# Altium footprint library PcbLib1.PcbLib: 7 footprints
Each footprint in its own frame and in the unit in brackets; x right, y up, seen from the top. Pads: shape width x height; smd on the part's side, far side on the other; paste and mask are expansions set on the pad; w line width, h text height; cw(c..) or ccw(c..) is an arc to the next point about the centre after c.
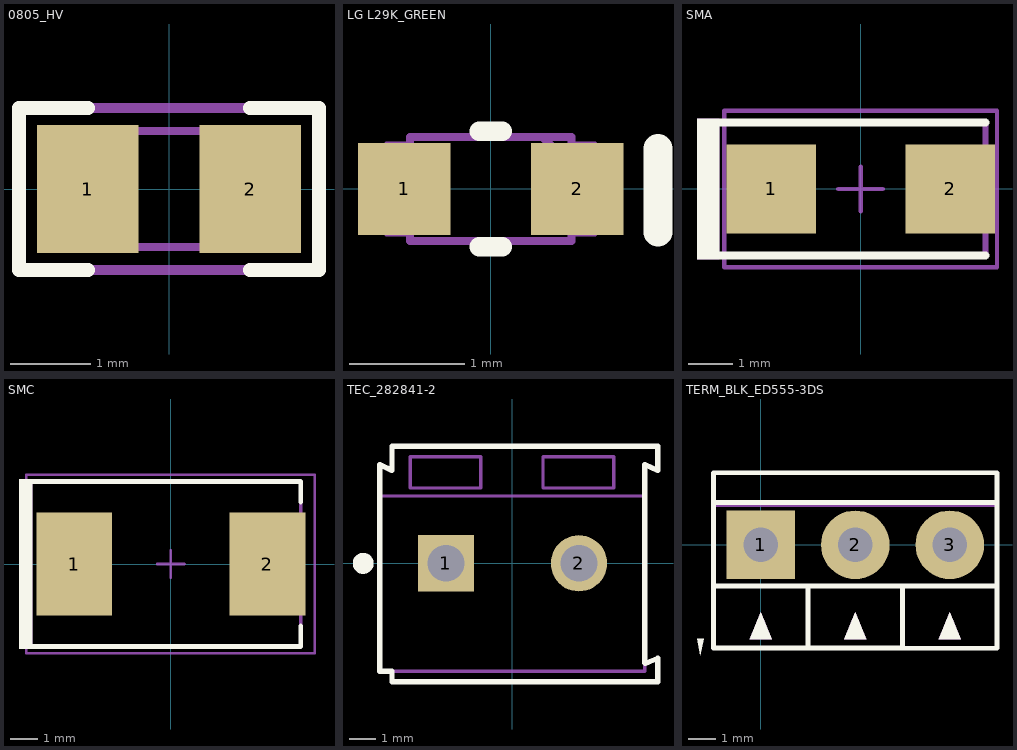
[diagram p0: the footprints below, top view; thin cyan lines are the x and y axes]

## 0805_HV [mil] "0805 with 30mil clearance between pads"
height 57.09
pads (2):
  rect 50x63 smd: 1(-40,0) 2(40,0)
Top Overlay:
  lines w7: -40,-40 -74,-40 -74,0 -74,40 -40,40 ; 40,-40 74,-40 74,0 74,40 40,40
M5 Assembly Top:
  lines w5: -74,-40 74,-40 74,40 -74,40 -74,-40
  text ".Designator" at -64,-17 h35
M13 Component Bodies Top:
  lines w3.94: -25.59,-28.54 -25.59,28.54 ; 25.59,-28.54 25.59,28.54 ; -43.31,-28.54 43.31,-28.54 43.31,28.54 -43.31,28.54 -43.31,-28.54
3D body: height 57.09, standoff 0, extent -43.29,-28.52 -25.61,28.52
3D body: height 57.09, standoff 0, extent -25.57,-28.52 25.57,28.52
3D body: height 57.09, standoff 0, extent 25.61,-28.52 43.29,28.52

## LG L29K_GREEN [mm] "OSRAM"
height 0.67
pads (2):
  rect 0.8x0.8 smd paste-0.4: 1(-0.75,0) 2(0.75,0)
Top Overlay:
  lines w0.17: -0.1,-0.5 0.1,-0.5 ; -0.1,0.5 0.1,0.5
  lines w0.25: 1.45,-0.375 1.45,0.35
Top Paste:
  rectangle: -1.1,-0.35 -0.5,0.35
  rectangle: 0.5,-0.35 1.1,0.35
M5 Assembly Top:
  lines w0.07: 0.7,0.375 0.9,0.375 0.9,-0.375 0.7,-0.375 ; 0.7,-0.375 0.7,0.2 ; 0.7,-0.375 0.7,-0.45 -0.7,-0.45 -0.7,-0.375 -0.9,-0.375 -0.9,0.375 -0.7,0.375 -0.7,0.45 0.7,0.45 ; 0.7,0.2 0.45,0.45 0.7,0.45 ; 0.7,0.2 0.7,0.45
  text ".Designator" at -0.75,-0.2 h0.35
3D body: height 0.18, standoff 0, extent -0.899,-0.374 -0.701,0.374
3D body: height 0.18, standoff 0, extent 0.701,-0.374 0.899,0.374
3D body: height 0.18, standoff 0, extent -0.699,-0.449 0.699,0.449
3D body: height 0.67, standoff 0.18, extent -0.699,-0.449 0.699,0.449
3D body: height 0.67, standoff 0.65, extent 0.451,0.201 0.699,0.449

## PCBComponent_1 [mm]
M5 Assembly Top:
  text ".Designator" at -1.8,-0.514 h1.02

## SMA [mm] "Molded Diode, 2-Leads, Body 4.3x2.6mm, IPC Medium Density, based on OnSemi component dimensions and land pattern"
height 2.27
pads (2):
  rect 2x2 smd: 1(-2,0) 2(2,0)
Top Overlay:
  rectangle: -3.658,-1.575 -3.15,1.575
  lines w0.178: -3.327,-1.486 2.794,-1.486 ; -3.327,1.486 2.794,1.486
M5 Assembly Top:
  rectangle: -3.658,-1.575 -3.15,1.575
  lines w0.127: -3.327,-1.486 2.794,-1.486 2.794,1.486 -3.327,1.486
  text ".Designator" at -2.769,-0.33 h1.02
M15 Courtyards Top:
  lines w0.1: -0.5,0 0.5,0 ; 0,-0.5 0,0.5 ; -3.05,-1.75 -3.05,1.75 3.05,1.75 3.05,-1.75 -3.05,-1.75
3D body "SMA_nominal.stp": height 2.42, standoff 0.02, extent -2.6,-1.3 2.6,1.3

## SMC [mil] "Molded Diode, 2-Leads, Body 6.9x5.8mm, IPC Medium Density, based on OnSemi component dimensions and land patterns"
height 94.88
pads (2):
  rect 110x150 smd: 1(-140.49,0) 2(140.49,0)
Top Overlay:
  rectangle: -221,-123.5 -201,123.5
  lines w7: -210,-120 189,-120 189,-90.25 ; -210,120 189,120 189,90.25
M5 Assembly Top:
  rectangle: -221,-123.5 -201,123.5
  lines w5: -210,-120 189,-120 189,120 -210,120
  text ".Designator" at -85,-20 h40
M15 Courtyards Top:
  lines w3.94: -19.69,0 19.68,0 ; 0,-19.68 0,19.68 ; -210.46,-129.92 209.38,-129.92 209.38,129.92 -210.46,129.92 -210.46,-129.92
3D body "SMC_nominal.stp": height 91.35, standoff 0.6, extent -156.49,-116.13 156.5,116.15

## TEC_282841-2 [mm] "TE Connectivity"
height 15.45
pads (2):
  rect 2.15x2.15 hole 1.4: 1(-2.54,0)
  round 2.15 hole 1.4: 2(2.54,0)
Top Overlay:
  circle w0.4: c-5.7,0 r0.2
  lines w0.203: 5.05,-3.8 5.05,3.775 5.55,3.55 5.55,4.475 -4.6,4.475 -4.6,3.55 -5.075,3.775 -5.075,-4.125 -4.6,-4.125 -4.6,-4.525 5.55,-4.525 5.55,-3.625 5.075,-3.825
M5 Assembly Top:
  circle w0.4: c-2.55,0.025 r0.2
  lines w0.127: 5.06,-3.825 5.56,-3.625 5.56,-4.525 -4.61,-4.525 -4.61,-4.125 ; -5.1,2.575 5.06,2.575 ; -5.1,2.575 -5.1,3.775 -4.61,3.575 -4.61,4.475 5.56,4.475 5.56,3.575 5.06,3.775 5.06,2.575 ; -5.1,2.575 -5.1,2.292 -5.1,2.093 -5.1,-3.051 -5.1,-3.249 -5.1,-4.125 -4.61,-4.125 ; -4.61,-4.125 5.06,-4.125 5.06,-3.249 5.06,-3.051 5.06,2.093 5.06,2.292 5.06,2.575 ; -3.91,2.875 -3.91,4.075 -1.21,4.075 -1.21,2.875 -3.91,2.875 ; 1.17,2.875 3.87,2.875 3.87,4.075 1.17,4.075 1.17,2.875
  text ".Designator" at -1.7,-0.475 h1.02
3D body "TEC-282841-2.stp": height 15.2, standoff -3.5, extent -5.08,-4.525 5.58,4.475

## TERM_BLK_ED555-3DS [mm]
height 8.2
pads (3):
  rect 2.54x2.54 hole 1.27: 1(0,0)
  round 2.54 hole 1.27: 2(3.5,0) 3(7,0)
Top Overlay:
  region: 0.4,-3.5 -0.4,-3.5 0,-2.5
  region: 3.9,-3.5 3.1,-3.5 3.5,-2.5
  region: 7.4,-3.5 6.6,-3.5 7,-2.5
  region: -2.235,-4.089 -2.108,-3.48 -2.362,-3.48
  lines w0.178: -1.752,1.572 1.748,1.572 5.248,1.572 8.748,1.572 ; 1.75,-3.815 1.75,-1.528 ; 5.25,-3.815 5.25,-1.528 ; 5.25,-3.81 -1.75,-3.81 -1.75,2.667 5.25,2.667 ; -1.752,-1.528 -1.752,1.472 -1.752,2.672 1.748,2.672 5.248,2.672 8.748,2.672 8.748,1.472 8.748,-1.528 ; -1.752,-1.528 1.748,-1.528 5.248,-1.528 8.748,-1.528 ; -1.752,-1.528 -1.752,-3.828 1.748,-3.828 5.248,-3.828 8.748,-3.828 8.748,-1.528
M5 Assembly Top:
  region: 7.4,-3.5 6.6,-3.5 7,-2.5
  region: 3.9,-3.5 3.1,-3.5 3.5,-2.5
  region: 0.4,-3.5 -0.4,-3.5 0,-2.5
  lines w0.127: 1.75,-3.815 1.75,-1.528 ; 5.25,-3.815 5.25,-1.528 ; 5.25,-3.81 -1.75,-3.81 -1.75,2.667 5.25,2.667 ; -1.752,-1.528 -1.752,-3.828 1.748,-3.828 5.248,-3.828 8.748,-3.828 8.748,-1.528 ; -1.752,-1.528 1.748,-1.528 5.248,-1.528 8.748,-1.528 ; -1.752,-1.528 -1.752,1.472 ; -1.752,1.472 1.748,1.472 5.248,1.472 8.748,1.472 ; -1.752,1.472 -1.752,2.672 1.748,2.672 5.248,2.672 8.748,2.672 8.748,1.472 ; 8.748,-1.528 8.748,1.472
  text ".Designator" at 0.3,-0.3 h1.02
3D body "On-Shore_ED555_3DS.stp": height 8.2, standoff -3.5, extent -1.752,-3.828 8.748,2.672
